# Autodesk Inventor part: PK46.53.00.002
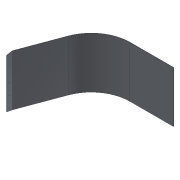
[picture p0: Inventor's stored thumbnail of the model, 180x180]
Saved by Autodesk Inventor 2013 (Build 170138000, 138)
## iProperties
Created: 2005-03
Part Number: PK46.53.00.002
Material: Steel, Mild
Document SubType Name: Обычные детали
Designer: HKostja
Manufacturer: Standard
Standards Organization: Custom
Density: 7.86 g/cm^3
Sheet Metal Rule: По умолчанию
Mass: 16132.9 g
Surface Area: 13800.9 cm^2
Volume: 2052.54 cm^3
Author: HKostja
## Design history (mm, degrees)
node "ФлнОтгиб1"
sketch "Эскиз2" dims "d25" = 10
  geometry: L1 (0, 0)-(500, 0) reference; L2 (0, 54.461)-(0, 0) reference; L3 (500, 0)-(500, 54.461) reference; L4 (490, 0)-(500, 55); L5 (10, 0)-(0, 55); L6 (500, 55)-(500, 54.461); L7 (0, 55)-(0, 54.461); C1 r 6 at (30, 25); C2 r 6 at (140, 25); C3 r 6 at (250, 25); C4 r 6 at (360, 25); C5 r 6 at (470, 25)
  constraints: 8 end point, 5 centre point, 4 point on line, 1 collinear, 1 horizontal, 8 other
  dimensions: "d17" = 12 diameter of C1; "d18" = 30 distance from line of C1.centre L2; "d19" = 25 distance from line of C1.centre L1; "d22" = 110 distance of C1.centre C2.centre; "d27" = 30 horizontal distance of C5.centre L1.end (derived); "d30" = 10 distance from line of L3 L4.start; "d31" = 10 distance from line of L2 L5.start (= d30); "d32" = 55 distance from line of L1 L5.end; "d33" = 55 distance from line of L1 L4.end (= d32)
extrude "Выдавливание2" cut sketch "Эскиз2" stored distance "d28" = 10; taper "d29" = 0 deg
body "Solid1"
sketch "Эскиз1"
  geometry: L1 (264.331, 0)-(690, 0); L2 (-240, -646.916)-(-91.941, -247.826); L3 (-240, -646.916)-(-240, -701.916); A1 r 380 centre (264.331, -380) between (264.331, 0) and (-91.941, -247.826); 1 further point
  constraints: 6 end point, 2 point on circle, 2 point on line, 2 tangent, 1 centre point, 1 equal length, 1 horizontal, 1 perpendicular, 1 other
  dimensions: "d0" = 690 distance of point (0, 0) L1.end; "d3" = 240 horizontal distance of point (0, 0) L2.start; "d6" = 380 radius of A1; "d9" = 55 distance of L2.start L3.end
feature "Плакирование1" dims "d10" = 500, "d11" = 3 (= Ширина_просечки), "d13" = 6 (= Минимальный_остаток), "d15" = 3 (= Радиус_гибки), "d16" = 3, "Толщина" = 3
feature "Изгиб1" dims "d11" = 3 (= Ширина_просечки), "d12" = 1.5 (= Глубина_просечки), "d13" = 6 (= Минимальный_остаток), "d14" = 3 (= Радиус_гибки), "d15" = 3 (= Радиус_гибки), "d16" = 3, "Толщина" = 3, "Зазор_стыка" = 0.01
other parameters: "Радиус_гибки" = 3 (= Толщина), "Ширина_просечки" = 3 (= Толщина), "Глубина_просечки" = 1.5 (= 0.5 x Толщина), "Размер_высечки" = 12 (= 4 x Толщина), "Минимальный_остаток" = 6 (= 2 x Толщина), "Радиус_перехода" = 3 (= Радиус_гибки), "JacobiRadiusSize" = 3 (= Толщина), "GapSize" = 3 (= Толщина)
